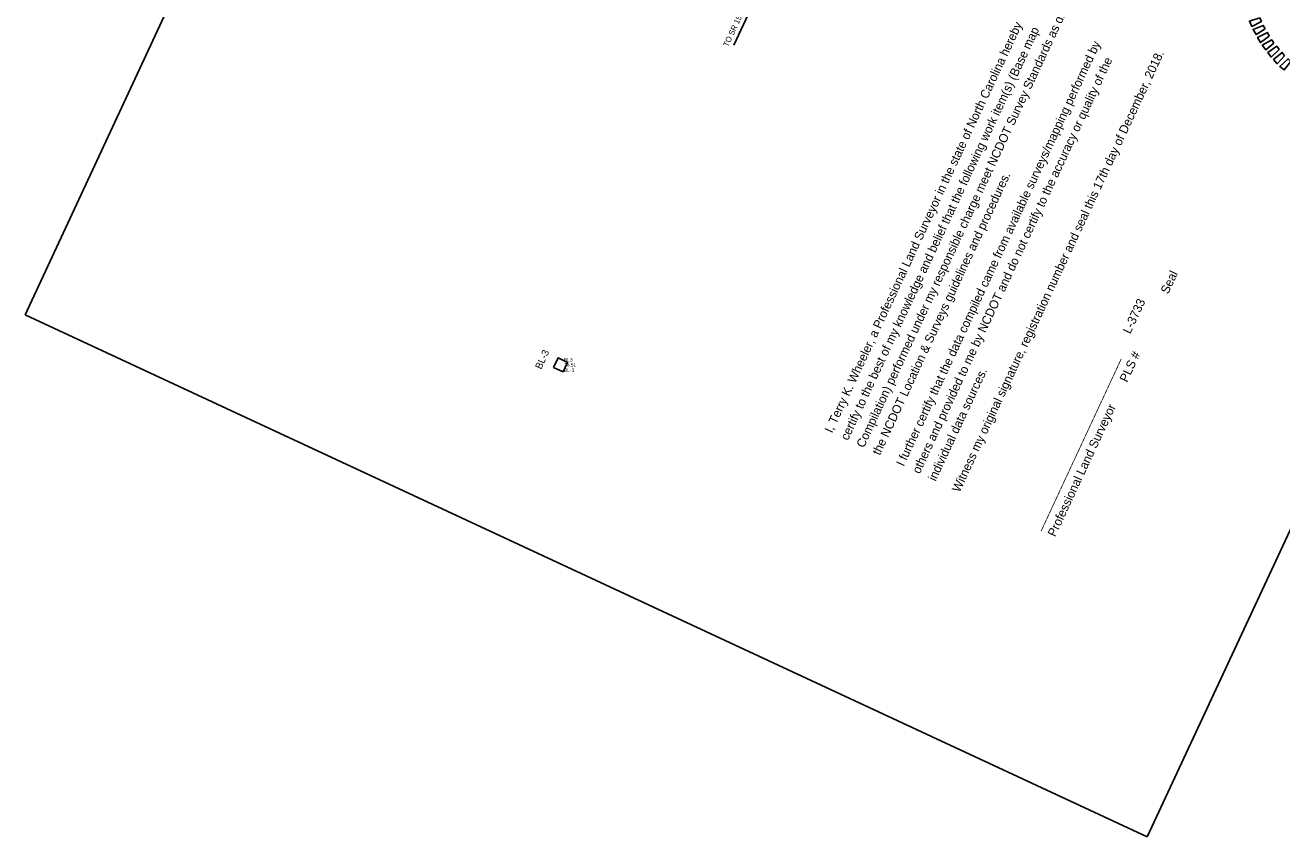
# Model space of a CAD drawing. Extents: x 2532037 to 2533565, y 713396 to 716867.
# Drawn here: x 2532199 to 2533093, y 714704 to 715282 of the extents above; entities that cross this region are included whole.
import ezdxf

# ---------------------------------------------------------------- set-up
doc = ezdxf.new("R2010")
doc.units = 0
for name, color, linetype in [('CTL Secondary Horizontal and Vertical CELL', 7, 'Continuous'), ('CTL Secondary Horizontal and Vertical Cogo Comment', 7, 'Continuous'), ('CTL Secondary Horizontal and Vertical Cogo Elevation', 7, 'Continuous'), ('CTL Secondary Horizontal and Vertical Cogo Number', 7, 'Continuous'), ('CTL Secondary Horizontal and Vertical Text', 7, 'Continuous'), ('Exist Roads Soil Text', 7, 'Continuous'), ('EXIST SURVEY STATEMENT CELL', 7, 'Continuous'), ('Sheet PDF Layout', 7, 'Continuous'), ('Sheet Professional Seal CELL', 7, 'Continuous')]:
    doc.layers.add(name, color=color, linetype=linetype)

msp = doc.modelspace()

# ---------------------------------------------------------------- linework, layer by layer
at = {"layer": 'CTL Secondary Horizontal and Vertical CELL'}
msp.add_line((2532579.78, 715039.99), (2532579.78, 715039.99), dxfattribs=at)
msp.add_lwpolyline([(2532574.88, 715038.22), (2532578, 715044.94), (2532584.73, 715041.81), (2532581.61, 715035.09)], close=True, dxfattribs=at)
at = {"layer": 'Exist Roads Soil Text'}
msp.add_line((2532703.06, 715267.27), (2532714.86, 715292.63), dxfattribs=at)
at = {"layer": 'Sheet PDF Layout'}
for p, q in [((2532199.09, 715075.6), (2532767.38, 716297.08)), ((2533565.25, 715925.87), (2532996.96, 714704.4)), ((2532996.96, 714704.4), (2532199.09, 715075.6))]:
    msp.add_line(p, q, dxfattribs=at)
at = {"layer": 'Sheet Professional Seal CELL'}
for points in [[(2533078.25, 715284.3), (2533071.32, 715280.72), (2533069.66, 715284.45), (2533077.03, 715286.75)], [(2533080.79, 715279.08), (2533074.3, 715275.02), (2533072.16, 715278.58), (2533079.41, 715281.47)], [(2533083.55, 715273.75), (2533077.39, 715269.26), (2533075.4, 715272.88), (2533082.44, 715276.42)], [(2533086.94, 715268.91), (2533081.27, 715264.06), (2533078.7, 715267.3), (2533085.52, 715271.2)], [(2533090.87, 715264.35), (2533085.15, 715258.85), (2533082.59, 715262.09), (2533089.02, 715266.58)], [(2533094.59, 715259.9), (2533089.41, 715254.14), (2533086.73, 715257.16), (2533092.89, 715262.18)], [(2533098.99, 715255.77), (2533094.35, 715249.75), (2533091.15, 715252.23), (2533097.14, 715257.73)]]:
    msp.add_lwpolyline(points, close=True, dxfattribs=at)

# ---------------------------------------------------------------- texts
at = {"layer": 'CTL Secondary Horizontal and Vertical Cogo Comment'}
msp.add_text('BL-3', height=2.5, dxfattribs=at).set_placement((2532582.28, 715034.99))
at = {"layer": 'CTL Secondary Horizontal and Vertical Cogo Elevation'}
msp.add_text('26.51', height=2.5, dxfattribs=at).set_placement((2532582.28, 715038.74))
msp.add_text('26.51', height=2.5, dxfattribs=at).set_placement((2532582.28, 715038.74))
at = {"layer": 'CTL Secondary Horizontal and Vertical Cogo Number'}
msp.add_text('BL3', height=2.5, dxfattribs=at).set_placement((2532582.28, 715042.49))
msp.add_text('BL3', height=2.5, dxfattribs=at).set_placement((2532582.28, 715042.49))
at = {"layer": 'CTL Secondary Horizontal and Vertical Text'}
msp.add_text('BL-3', height=5, rotation=65.05, dxfattribs=at).set_placement((2532565.98, 715036.48))
at = {"layer": 'Exist Roads Soil Text'}
msp.add_text('TO SR 1550', height=4, rotation=65.05, dxfattribs=at).set_placement((2532698.87, 715265.82))
at = {"layer": 'EXIST SURVEY STATEMENT CELL'}
for s, p in [('Compilation) performed under my responsible charge meet NCDOT Survey Standards as directed in', (2532795.49, 714980.57)), ('I, Terry K. Wheeler, a Professional Land Surveyor in the state of North Carolina hereby', (2532772.82, 714991.12)), ('certify to the best of my knowledge and belief that the following work item(s) (Base map', (2532784.16, 714985.84)), ('I further certify that the data compiled came from available surveys/mapping performed by', (2532823.82, 714967.39)), ('others and provided to me by NCDOT and do not certify to the accuracy or quality of the', (2532835.16, 714962.12)), ('Witness my original signature, registration number and seal this 17th day of December, 2018.', (2532863.49, 714948.93)), ('the NCDOT Location & Surveys guidelines and procedures.', (2532806.82, 714975.3)), ('Professional Land Surveyor        PLS #                    Seal', (2532931.49, 714917.3)), ('_____________________________        L-3733', (2532920.16, 714922.57)), ('individual data sources.', (2532846.49, 714956.84))]:
    msp.add_text(s, height=6.25, rotation=65.05, dxfattribs=at).set_placement(p)

doc.saveas('drawing.dxf')
